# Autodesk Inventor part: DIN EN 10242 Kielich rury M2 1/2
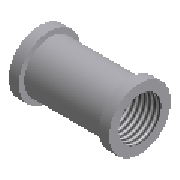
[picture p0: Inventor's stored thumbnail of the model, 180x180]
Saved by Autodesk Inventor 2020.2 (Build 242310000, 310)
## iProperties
Manager: www.cadconsulting.pl
Company: Fabian Stasiak CAD Consulting
IsCustomPart: 0
NAME: PIPING: DIN EN 10242 Socket M2
DATA: <meta><inlinegroups number="1" deflen="2.7"></inlinegroups><connections number="2"></connections><angles><a>3.14159265358979</a></angles></meta>
Created: 2014-02
Part Number: DIN EN 10242 Kielich rury M2 1/2
Material: Żelazo, ciągliwe
Description: Kielich
Document SubType Name: Modeling
Standard: DIN EN 10242
Designer: F.Stasiak
Standards Organization: DIN
Language: pl-PL
Size Designation: 1/2
Categories: <MemberInstance><Categories><Category DisplayName="Rury cienko- i grubościenne" InternalName="4347fa0f-2144-441d-94cd-e3e15c92b736" Mnemonic="TUBEANDPIPE"><Cate
Density: 7.15 g/cm^3
Appearance: Częściowo polerowana
Catalog Web Link: www.expertbooks.pl
Author: F.Stasiak
Subject: Zbiór ćwiczeń. Autodesk Inventor 2020. Kurs Professional
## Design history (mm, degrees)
sketch "Sketch1"
  geometry: L1 (0, 13.02)-(4.34, 13.02); L2 (4.34, 13.02)-(4.34, 10.85); L3 (4.34, 10.85)-(18, 10.85); L4 (18, 0)-(0, 0); L5 (0, 13.02)-(0, 9.316); L6 (0, 9.316)-(13, 9.316); L7 (13, 9.316)-(18, 9.316); L8 (18, 9.316)-(18, 10.85); L9 (0, 9.316)-(0, 0); L10 (18, 9.316)-(18, 0); L11 (36, 13.02)-(36, 9.316); L12 (36, 13.02)-(31.66, 13.02); L13 (31.66, 13.02)-(31.66, 10.85); L14 (31.66, 10.85)-(18, 10.85); L15 (36, 9.316)-(23, 9.316); L16 (23, 9.316)-(18, 9.316); L17 (36, 9.316)-(36, 0); L18 (18, 0)-(36, 0); L19 (13, 9.316)-(13, 0); L20 (23, 9.316)-(23, 0)
  constraints: 40 end point, 6 parallel, 6 symmetric about line, 4 perpendicular, 2 point on line, 1 horizontal, 1 vertical, 9 other
  dimensions: "d0" = 26.04 diameter of L1.start L4 (= H); "d1" = 18.631 diameter of L5.end L4 (= MD); "d2" = 4.34 distance of L1.start L1.end (= EE); "d3" = 10 distance of L15.end L6.end (= Z1); "d4" = 36 distance of L11.start L1.start (= A); "d5" = 21.7 diameter of L13.end L18 (= D)
revolve "Revolution1" sketch "Sketch1" stored, may be unused: angle "d8" = 90 deg
workpoint "Work Point1"
workpoint "Work Point2"
workaxis "Work Axis1"
workpoint "Work Point3"
workaxis "Work Axis2"
workpoint "Work Point4"
body "Solid1"
feature "Gwint1" dims "d13" = 13 (= -0.5 x Z1 + 0.5 x A), "d14" = 0
feature "Gwint2" dims "d15" = 13 (= -0.5 x Z1 + 0.5 x A), "d16" = 0
other parameters: "EE" = 4.34 (= 0.2 x D) [user parameter; used in 1 equation term], "D" = 21.7 [user parameter; used in 3 equation terms], "A" = 36 [user parameter; used in 3 equation terms], "Z1" = 10 [user parameter; used in 3 equation terms], "H" = 26.04 (= 1.2 x D) [user parameter; used in 1 equation term], "MD" = 18.631 [user parameter; used in 1 equation term], "Size_Designation" = 5 [user parameter]
